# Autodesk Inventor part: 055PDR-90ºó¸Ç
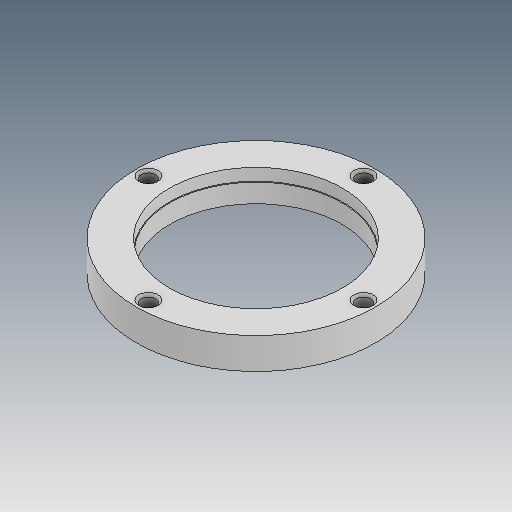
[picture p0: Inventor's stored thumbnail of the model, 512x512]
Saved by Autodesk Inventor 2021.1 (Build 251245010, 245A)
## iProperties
Created: 2019-04
Part Number: 055PDR-90ºó¸Ç
Material: Ogólny
Document SubType Name: Modeling
Designer: user
Density: 1 g/cm^3
Appearance: Domyślna
Author: user
Revision Number: ÈÎºÎ
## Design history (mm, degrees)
feature "µ¹½Ç1"
node "Bryła1"
